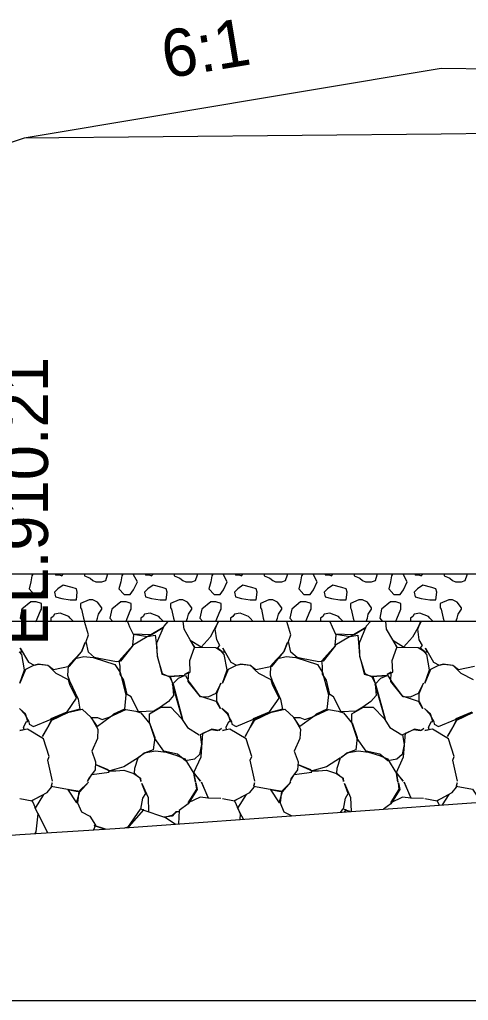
# Model space of a CAD drawing. Extents: x -26 to 4781, y -31 to 24738.
# Drawn here: x 2269.09 to 2278.57, y 7500 to 7520.71 of the extents above; entities that cross this region are included whole.
import ezdxf

# ---------------------------------------------------------------- set-up
doc = ezdxf.new("R2010")
doc.units = 0
for name, color, linetype in [('DESIGN - SHEET - Light Grid', 7, 'Continuous'), ('DESIGN - TRANSPORTATION - Proposed Layout Patterning', 7, 'Continuous'), ('DESIGN - TYPICAL - Finished Grade and Subgrade', 7, 'Continuous'), ('DESIGN - TYPICAL - Finished Grade Slopes Text', 7, 'Continuous'), ('DESIGN - TYPICAL - Subgrade Tie Text', 7, 'Continuous'), ('GEOTECHNICAL – SCRATCH – Level 1', 7, 'Continuous'), ('SURVEY - GROUND - Top of Ground', 7, 'Continuous')]:
    doc.layers.add(name, color=color, linetype=linetype)

msp = doc.modelspace()

# ---------------------------------------------------------------- linework, layer by layer
at = {"layer": 'DESIGN - SHEET - Light Grid'}
msp.add_line((2000, 7500), (2300, 7500), dxfattribs=at)
at = {"layer": 'DESIGN - TRANSPORTATION - Proposed Layout Patterning'}
for p, q in [((2269.33, 7508.419), (2269.14, 7508.259)), ((2271.23, 7508.419), (2271.04, 7508.259)), ((2273.13, 7508.419), (2272.94, 7508.259)), ((2275.03, 7508.419), (2274.84, 7508.259)), ((2276.93, 7508.419), (2276.74, 7508.259)), ((2270.38, 7508.289), (2270.4, 7508.259)), ((2272.28, 7508.289), (2272.3, 7508.259)), ((2274.18, 7508.289), (2274.2, 7508.259)), ((2276.08, 7508.289), (2276.1, 7508.259)), ((2277.98, 7508.289), (2278, 7508.259))]:
    msp.add_line(p, q, dxfattribs=at)
for points in [[(2269.33, 7508.839), (2269.29, 7508.689), (2269.4, 7508.569), (2269.53, 7508.569), (2269.6, 7508.669), (2269.68, 7508.839), (2269.6, 7508.989), (2269.589, 7509)], [(2269.373, 7509), (2269.35, 7508.969), (2269.33, 7508.839)], [(2269.845, 7509), (2269.85, 7508.989), (2269.93, 7508.989), (2269.98, 7508.969), (2270.011, 7509)], [(2270.46, 7509), (2270.46, 7508.969), (2270.53, 7508.939), (2270.58, 7508.919), (2270.64, 7508.869)], [(2270.64, 7508.869), (2270.7, 7508.839), (2270.83, 7508.839), (2270.91, 7508.869), (2270.95, 7508.989), (2270.95, 7509)], [(2271.23, 7508.839), (2271.19, 7508.689), (2271.3, 7508.569), (2271.43, 7508.569), (2271.5, 7508.669), (2271.58, 7508.839), (2271.5, 7508.989), (2271.489, 7509)], [(2271.273, 7509), (2271.25, 7508.969), (2271.23, 7508.839)], [(2271.745, 7509), (2271.75, 7508.989), (2271.83, 7508.989), (2271.88, 7508.969), (2271.911, 7509)], [(2272.36, 7509), (2272.36, 7508.969), (2272.43, 7508.939), (2272.48, 7508.919), (2272.54, 7508.869)], [(2272.54, 7508.869), (2272.6, 7508.839), (2272.73, 7508.839), (2272.81, 7508.869), (2272.85, 7508.989), (2272.85, 7509)], [(2273.13, 7508.839), (2273.09, 7508.689), (2273.2, 7508.569), (2273.33, 7508.569), (2273.4, 7508.669), (2273.48, 7508.839), (2273.4, 7508.989), (2273.389, 7509)], [(2273.173, 7509), (2273.15, 7508.969), (2273.13, 7508.839)], [(2273.645, 7509), (2273.65, 7508.989), (2273.73, 7508.989), (2273.78, 7508.969), (2273.811, 7509)], [(2274.26, 7509), (2274.26, 7508.969), (2274.33, 7508.939), (2274.38, 7508.919), (2274.44, 7508.869)], [(2274.44, 7508.869), (2274.5, 7508.839), (2274.63, 7508.839), (2274.71, 7508.869), (2274.75, 7508.989), (2274.75, 7509)], [(2275.03, 7508.839), (2274.99, 7508.689), (2275.1, 7508.569), (2275.23, 7508.569), (2275.3, 7508.669), (2275.38, 7508.839), (2275.3, 7508.989), (2275.289, 7509)], [(2275.073, 7509), (2275.05, 7508.969), (2275.03, 7508.839)], [(2275.545, 7509), (2275.55, 7508.989), (2275.63, 7508.989), (2275.68, 7508.969), (2275.711, 7509)], [(2276.16, 7509), (2276.16, 7508.969), (2276.23, 7508.939), (2276.28, 7508.919), (2276.34, 7508.869)], [(2276.34, 7508.869), (2276.4, 7508.839), (2276.53, 7508.839), (2276.61, 7508.869), (2276.65, 7508.989), (2276.65, 7509)], [(2276.93, 7508.839), (2276.89, 7508.689), (2277, 7508.569), (2277.13, 7508.569), (2277.2, 7508.669), (2277.28, 7508.839), (2277.2, 7508.989), (2277.189, 7509)], [(2276.973, 7509), (2276.95, 7508.969), (2276.93, 7508.839)], [(2277.445, 7509), (2277.45, 7508.989), (2277.53, 7508.989), (2277.58, 7508.969), (2277.611, 7509)], [(2278.06, 7509), (2278.06, 7508.969), (2278.13, 7508.939), (2278.18, 7508.919), (2278.24, 7508.869)], [(2278.24, 7508.869), (2278.3, 7508.839), (2278.43, 7508.839), (2278.51, 7508.869), (2278.55, 7508.989), (2278.55, 7509)], [(2270.29, 7508.689), (2270.2, 7508.719), (2270.01, 7508.769), (2269.9, 7508.689), (2269.83, 7508.619), (2269.85, 7508.519), (2269.98, 7508.489), (2270.16, 7508.459), (2270.29, 7508.459), (2270.31, 7508.619), (2270.29, 7508.689)], [(2272.19, 7508.689), (2272.1, 7508.719), (2271.91, 7508.769), (2271.8, 7508.689), (2271.73, 7508.619), (2271.75, 7508.519), (2271.88, 7508.489), (2272.06, 7508.459), (2272.19, 7508.459), (2272.21, 7508.619), (2272.19, 7508.689)], [(2274.09, 7508.689), (2274, 7508.719), (2273.81, 7508.769), (2273.7, 7508.689), (2273.63, 7508.619), (2273.65, 7508.519), (2273.78, 7508.489), (2273.96, 7508.459), (2274.09, 7508.459), (2274.11, 7508.619), (2274.09, 7508.689)], [(2275.99, 7508.689), (2275.9, 7508.719), (2275.71, 7508.769), (2275.6, 7508.689), (2275.53, 7508.619), (2275.55, 7508.519), (2275.68, 7508.489), (2275.86, 7508.459), (2275.99, 7508.459), (2276.01, 7508.619), (2275.99, 7508.689)], [(2277.89, 7508.689), (2277.8, 7508.719), (2277.61, 7508.769), (2277.5, 7508.689), (2277.43, 7508.619), (2277.45, 7508.519), (2277.58, 7508.489), (2277.76, 7508.459), (2277.89, 7508.459), (2277.91, 7508.619), (2277.89, 7508.689)], [(2269.55, 7508.259), (2269.55, 7508.379), (2269.44, 7508.419), (2269.33, 7508.419)], [(2270.64, 7508.459), (2270.58, 7508.459), (2270.56, 7508.459), (2270.38, 7508.379), (2270.38, 7508.289)], [(2270.83, 7508.259), (2270.83, 7508.289), (2270.74, 7508.409), (2270.64, 7508.459)], [(2271.45, 7508.259), (2271.45, 7508.379), (2271.34, 7508.419), (2271.23, 7508.419)], [(2272.54, 7508.459), (2272.48, 7508.459), (2272.46, 7508.459), (2272.28, 7508.379), (2272.28, 7508.289)], [(2272.73, 7508.259), (2272.73, 7508.289), (2272.64, 7508.409), (2272.54, 7508.459)], [(2273.35, 7508.259), (2273.35, 7508.379), (2273.24, 7508.419), (2273.13, 7508.419)], [(2274.44, 7508.459), (2274.38, 7508.459), (2274.36, 7508.459), (2274.18, 7508.379), (2274.18, 7508.289)], [(2274.63, 7508.259), (2274.63, 7508.289), (2274.54, 7508.409), (2274.44, 7508.459)], [(2275.25, 7508.259), (2275.25, 7508.379), (2275.14, 7508.419), (2275.03, 7508.419)], [(2276.34, 7508.459), (2276.28, 7508.459), (2276.26, 7508.459), (2276.08, 7508.379), (2276.08, 7508.289)], [(2276.53, 7508.259), (2276.53, 7508.289), (2276.44, 7508.409), (2276.34, 7508.459)], [(2277.15, 7508.259), (2277.15, 7508.379), (2277.04, 7508.419), (2276.93, 7508.419)], [(2278.24, 7508.459), (2278.18, 7508.459), (2278.16, 7508.459), (2277.98, 7508.379), (2277.98, 7508.289)], [(2278.43, 7508.259), (2278.43, 7508.289), (2278.34, 7508.409), (2278.24, 7508.459)], [(2269.14, 7508.259), (2269.1, 7508.069), (2269.163, 7508)], [(2269.429, 7508), (2269.44, 7508.009), (2269.53, 7508.229), (2269.55, 7508.259)], [(2270.13, 7508.109), (2269.95, 7508.179), (2269.83, 7508.159), (2269.8, 7508.109), (2269.75, 7508.069), (2269.75, 7508)], [(2270.4, 7508.259), (2270.44, 7508.069), (2270.462, 7508)], [(2270.712, 7508), (2270.74, 7508.069), (2270.76, 7508.159), (2270.83, 7508.259)], [(2271.04, 7508.259), (2271, 7508.069), (2271.063, 7508)], [(2271.329, 7508), (2271.34, 7508.009), (2271.43, 7508.229), (2271.45, 7508.259)], [(2272.03, 7508.109), (2271.85, 7508.179), (2271.73, 7508.159), (2271.7, 7508.109), (2271.65, 7508.069), (2271.65, 7508)], [(2272.3, 7508.259), (2272.34, 7508.069), (2272.362, 7508)], [(2272.612, 7508), (2272.64, 7508.069), (2272.66, 7508.159), (2272.73, 7508.259)], [(2272.94, 7508.259), (2272.9, 7508.069), (2272.963, 7508)], [(2273.229, 7508), (2273.24, 7508.009), (2273.33, 7508.229), (2273.35, 7508.259)], [(2273.93, 7508.109), (2273.75, 7508.179), (2273.63, 7508.159), (2273.6, 7508.109), (2273.55, 7508.069), (2273.55, 7508)], [(2274.2, 7508.259), (2274.24, 7508.069), (2274.262, 7508)], [(2274.512, 7508), (2274.54, 7508.069), (2274.56, 7508.159), (2274.63, 7508.259)], [(2274.84, 7508.259), (2274.8, 7508.069), (2274.863, 7508)], [(2275.129, 7508), (2275.14, 7508.009), (2275.23, 7508.229), (2275.25, 7508.259)], [(2275.83, 7508.109), (2275.65, 7508.179), (2275.53, 7508.159), (2275.5, 7508.109), (2275.45, 7508.069), (2275.45, 7508)], [(2276.1, 7508.259), (2276.14, 7508.069), (2276.162, 7508)], [(2276.412, 7508), (2276.44, 7508.069), (2276.46, 7508.159), (2276.53, 7508.259)], [(2276.74, 7508.259), (2276.7, 7508.069), (2276.763, 7508)], [(2277.029, 7508), (2277.04, 7508.009), (2277.13, 7508.229), (2277.15, 7508.259)], [(2277.73, 7508.109), (2277.55, 7508.179), (2277.43, 7508.159), (2277.4, 7508.109), (2277.35, 7508.069), (2277.35, 7508)], [(2278, 7508.259), (2278.04, 7508.069), (2278.062, 7508)], [(2278.312, 7508), (2278.34, 7508.069), (2278.36, 7508.159), (2278.43, 7508.259)], [(2270.229, 7508), (2270.16, 7508.069), (2270.13, 7508.109)], [(2271.367, 7508), (2271.415, 7507.891), (2271.495, 7507.721), (2271.475, 7507.501), (2271.785, 7507.681), (2271.895, 7507.731), (2272.125, 7507.871), (2271.865, 7507.721), (2271.495, 7507.731), (2271.795, 7507.681), (2271.955, 7507.711), (2271.975, 7507.561), (2271.995, 7507.281), (2272.095, 7506.891), (2272.275, 7506.841), (2272.325, 7506.691), (2272.345, 7506.441), (2272.235, 7506.311), (2272.065, 7506.191), (2271.925, 7506.111), (2271.605, 7506.091), (2271.445, 7506.411), (2271.365, 7506.461), (2271.295, 7506.761), (2271.215, 7506.891), (2271.215, 7507.061), (2271.195, 7507.171), (2271.485, 7507.491), (2271.225, 7507.161), (2271.135, 7507.151), (2270.765, 7507.221), (2270.675, 7507.241), (2270.545, 7507.351), (2270.495, 7507.581), (2270.545, 7507.721), (2270.459, 7508)], [(2272.224, 7508), (2272.135, 7507.901), (2271.985, 7507.541), (2271.995, 7507.271), (2272.105, 7506.901), (2272.255, 7506.831), (2272.335, 7506.681), (2272.535, 7505.941), (2272.325, 7506.681), (2272.445, 7506.801), (2272.575, 7506.861), (2272.245, 7506.841), (2272.595, 7506.861), (2272.675, 7506.721), (2272.895, 7506.431), (2273.255, 7506.311), (2273.335, 7506.161), (2273.255, 7506.301), (2273.255, 7506.481), (2273.345, 7506.701), (2273.235, 7506.481), (2273.065, 7506.401), (2272.915, 7506.411), (2272.655, 7506.731), (2272.665, 7506.931), (2272.575, 7506.881), (2272.695, 7506.931), (2272.685, 7507.181), (2272.785, 7507.451), (2272.965, 7507.461), (2273.235, 7507.451), (2273.365, 7507.371), (2273.275, 7507.441), (2273.325, 7507.491), (2273.255, 7507.611), (2273.225, 7507.841), (2273.285, 7507.991), (2273.294, 7508)], [(2272.129, 7508), (2272.06, 7508.069), (2272.03, 7508.109)], [(2273.294, 7508), (2273.195, 7507.821), (2273.115, 7507.671), (2272.925, 7507.461), (2272.695, 7507.601), (2272.785, 7507.461), (2272.695, 7507.611), (2272.565, 7507.841), (2272.548, 7508)], [(2274.029, 7508), (2273.96, 7508.069), (2273.93, 7508.109)], [(2275.647, 7508), (2275.695, 7507.891), (2275.775, 7507.721), (2275.755, 7507.501), (2276.065, 7507.681), (2276.175, 7507.731), (2276.405, 7507.871), (2276.145, 7507.721), (2275.775, 7507.731), (2276.075, 7507.681), (2276.235, 7507.711), (2276.255, 7507.561), (2276.275, 7507.281), (2276.375, 7506.891), (2276.555, 7506.841), (2276.605, 7506.691), (2276.625, 7506.441), (2276.515, 7506.311), (2276.345, 7506.191), (2276.205, 7506.111), (2275.885, 7506.091), (2275.725, 7506.411), (2275.645, 7506.461), (2275.575, 7506.761), (2275.495, 7506.891), (2275.495, 7507.061), (2275.475, 7507.171), (2275.765, 7507.491), (2275.505, 7507.161), (2275.415, 7507.151), (2275.045, 7507.221), (2274.955, 7507.241), (2274.825, 7507.351), (2274.775, 7507.581), (2274.825, 7507.721), (2274.739, 7508)], [(2275.929, 7508), (2275.86, 7508.069), (2275.83, 7508.109)], [(2276.504, 7508), (2276.415, 7507.901), (2276.265, 7507.541), (2276.275, 7507.271), (2276.385, 7506.901), (2276.535, 7506.831), (2276.615, 7506.681), (2276.815, 7505.941), (2276.605, 7506.681), (2276.725, 7506.801), (2276.855, 7506.861), (2276.525, 7506.841), (2276.875, 7506.861), (2276.955, 7506.721), (2277.175, 7506.431), (2277.535, 7506.311), (2277.615, 7506.161), (2277.535, 7506.301), (2277.535, 7506.481), (2277.625, 7506.701), (2277.515, 7506.481), (2277.345, 7506.401), (2277.195, 7506.411), (2276.935, 7506.731), (2276.945, 7506.931), (2276.855, 7506.881), (2276.975, 7506.931), (2276.965, 7507.181), (2277.065, 7507.451), (2277.245, 7507.461), (2277.515, 7507.451), (2277.645, 7507.371), (2277.555, 7507.441), (2277.605, 7507.491), (2277.535, 7507.611), (2277.505, 7507.841), (2277.565, 7507.991), (2277.574, 7508)], [(2277.574, 7508), (2277.475, 7507.821), (2277.395, 7507.671), (2277.205, 7507.461), (2276.975, 7507.601), (2277.065, 7507.461), (2276.975, 7507.611), (2276.845, 7507.841), (2276.828, 7508)], [(2277.829, 7508), (2277.76, 7508.069), (2277.73, 7508.109)], [(2269.785, 7504.631), (2269.685, 7505.071), (2269.715, 7505.151), (2269.595, 7505.521), (2269.255, 7505.731), (2269.095, 7505.701), (2269.185, 7505.721), (2269.175, 7505.771), (2269.235, 7505.891), (2269.265, 7505.891), (2269.215, 7506.051), (2269.085, 7506.161), (2269.195, 7506.051), (2269.285, 7505.891), (2269.295, 7505.831), (2269.385, 7505.781), (2269.755, 7505.941), (2270.105, 7506.071), (2269.765, 7505.911), (2269.685, 7505.771), (2269.575, 7505.571), (2269.685, 7505.761), (2269.755, 7505.911), (2269.755, 7505.951), (2270.095, 7506.091), (2270.295, 7506.381), (2270.155, 7506.671), (2270.125, 7506.771), (2269.865, 7506.901), (2269.785, 7506.981), (2269.695, 7507.071), (2269.485, 7507.101), (2269.385, 7507.071), (2269.215, 7506.991), (2269.095, 7506.701), (2269.195, 7506.981), (2269.135, 7507.301), (2269.085, 7507.361), (2269.145, 7507.361), (2269.105, 7507.441), (2269.275, 7507.141), (2269.395, 7507.081), (2269.495, 7507.101), (2269.685, 7507.081), (2269.805, 7506.991), (2270.145, 7507.061), (2270.395, 7507.361), (2270.475, 7507.561), (2270.395, 7507.361), (2270.235, 7507.191), (2270.115, 7507.061), (2270.105, 7506.871), (2270.145, 7506.751), (2270.325, 7506.361), (2270.365, 7506.151), (2270.105, 7506.081), (2270.415, 7506.151), (2270.605, 7505.971), (2270.745, 7505.731), (2270.735, 7505.531), (2270.615, 7505.261), (2270.695, 7505.041), (2270.685, 7504.871), (2270.545, 7504.681), (2270.525, 7504.621), (2270.615, 7504.771), (2270.985, 7504.821), (2270.965, 7504.871), (2270.705, 7504.971), (2270.995, 7504.851), (2271.125, 7504.851), (2271.295, 7504.861), (2271.505, 7504.791), (2271.645, 7504.691), (2271.655, 7504.621), (2271.645, 7504.681), (2271.515, 7504.801), (2271.525, 7504.901), (2271.595, 7505.121), (2271.295, 7504.931), (2270.995, 7504.851)], [(2274.065, 7504.631), (2273.965, 7505.071), (2273.995, 7505.151), (2273.875, 7505.521), (2273.535, 7505.731), (2273.375, 7505.701), (2273.465, 7505.721), (2273.455, 7505.771), (2273.515, 7505.891), (2273.545, 7505.891), (2273.495, 7506.051), (2273.365, 7506.161), (2273.475, 7506.051), (2273.565, 7505.891), (2273.575, 7505.831), (2273.665, 7505.781), (2274.035, 7505.941), (2274.385, 7506.071), (2274.045, 7505.911), (2273.965, 7505.771), (2273.855, 7505.571), (2273.965, 7505.761), (2274.035, 7505.911), (2274.035, 7505.951), (2274.375, 7506.091), (2274.575, 7506.381), (2274.435, 7506.671), (2274.405, 7506.771), (2274.145, 7506.901), (2274.065, 7506.981), (2273.975, 7507.071), (2273.765, 7507.101), (2273.665, 7507.071), (2273.495, 7506.991), (2273.375, 7506.701), (2273.475, 7506.981), (2273.415, 7507.301), (2273.365, 7507.361), (2273.425, 7507.361), (2273.385, 7507.441), (2273.555, 7507.141), (2273.675, 7507.081), (2273.775, 7507.101), (2273.965, 7507.081), (2274.085, 7506.991), (2274.425, 7507.061), (2274.675, 7507.361), (2274.755, 7507.561), (2274.675, 7507.361), (2274.515, 7507.191), (2274.395, 7507.061), (2274.385, 7506.871), (2274.425, 7506.751), (2274.605, 7506.361), (2274.645, 7506.151), (2274.385, 7506.081), (2274.695, 7506.151), (2274.885, 7505.971), (2275.025, 7505.731), (2275.015, 7505.531), (2274.895, 7505.261), (2274.975, 7505.041), (2274.965, 7504.871), (2274.825, 7504.681), (2274.805, 7504.621), (2274.895, 7504.771), (2275.265, 7504.821), (2275.245, 7504.871), (2274.985, 7504.971), (2275.275, 7504.851), (2275.405, 7504.851), (2275.575, 7504.861), (2275.785, 7504.791), (2275.925, 7504.691), (2275.935, 7504.621), (2275.925, 7504.681), (2275.795, 7504.801), (2275.805, 7504.901), (2275.875, 7505.121), (2275.575, 7504.931), (2275.275, 7504.851)], [(2278.685, 7506.771), (2278.425, 7506.901), (2278.345, 7506.981), (2278.255, 7507.071), (2278.045, 7507.101), (2277.945, 7507.071), (2277.775, 7506.991), (2277.655, 7506.701), (2277.755, 7506.981), (2277.695, 7507.301), (2277.645, 7507.361), (2277.705, 7507.361), (2277.665, 7507.441), (2277.835, 7507.141), (2277.955, 7507.081), (2278.055, 7507.101), (2278.245, 7507.081), (2278.365, 7506.991), (2278.705, 7507.061)], [(2270.265, 7507.221), (2270.445, 7507.261), (2270.645, 7507.241), (2271.105, 7507.091), (2271.215, 7506.921), (2271.335, 7506.451), (2271.305, 7506.151), (2271.075, 7506.041), (2271.005, 7505.981), (2270.735, 7505.781), (2270.605, 7505.971), (2270.735, 7505.971), (2270.835, 7505.931), (2270.985, 7505.981), (2271.335, 7506.141), (2271.545, 7506.111), (2271.655, 7506.071), (2271.845, 7505.841), (2271.945, 7505.551), (2271.915, 7505.291), (2271.745, 7505.231), (2271.605, 7505.131), (2271.725, 7505.231), (2271.965, 7505.271), (2272.185, 7505.241), (2272.415, 7505.171), (2272.585, 7505.101), (2272.775, 7504.791), (2272.805, 7504.611), (2272.775, 7504.801), (2272.915, 7504.631), (2272.775, 7504.811), (2272.925, 7505.141), (2272.965, 7505.641), (2273.145, 7505.721), (2273.275, 7505.701), (2273.355, 7505.741), (2273.305, 7505.701), (2273.155, 7505.731), (2272.985, 7505.641), (2272.905, 7505.611), (2272.935, 7505.401), (2272.895, 7505.191), (2272.785, 7505.091), (2272.595, 7505.061), (2272.425, 7505.201), (2272.135, 7505.261), (2271.945, 7505.531), (2271.835, 7505.871), (2271.835, 7506.051), (2272.075, 7506.191), (2272.285, 7506.191), (2272.515, 7505.951), (2272.635, 7505.761), (2272.885, 7505.611)], [(2274.545, 7507.221), (2274.725, 7507.261), (2274.925, 7507.241), (2275.385, 7507.091), (2275.495, 7506.921), (2275.615, 7506.451), (2275.585, 7506.151), (2275.355, 7506.041), (2275.285, 7505.981), (2275.015, 7505.781), (2274.885, 7505.971), (2275.015, 7505.971), (2275.115, 7505.931), (2275.265, 7505.981), (2275.615, 7506.141), (2275.825, 7506.111), (2275.935, 7506.071), (2276.125, 7505.841), (2276.225, 7505.551), (2276.195, 7505.291), (2276.025, 7505.231), (2275.885, 7505.131), (2276.005, 7505.231), (2276.245, 7505.271), (2276.465, 7505.241), (2276.695, 7505.171), (2276.865, 7505.101), (2277.055, 7504.791), (2277.085, 7504.611), (2277.055, 7504.801), (2277.195, 7504.631), (2277.055, 7504.811), (2277.205, 7505.141), (2277.245, 7505.641), (2277.425, 7505.721), (2277.555, 7505.701), (2277.635, 7505.741), (2277.585, 7505.701), (2277.435, 7505.731), (2277.265, 7505.641), (2277.185, 7505.611), (2277.215, 7505.401), (2277.175, 7505.191), (2277.065, 7505.091), (2276.875, 7505.061), (2276.705, 7505.201), (2276.415, 7505.261), (2276.225, 7505.531), (2276.115, 7505.871), (2276.115, 7506.051), (2276.355, 7506.191), (2276.565, 7506.191), (2276.795, 7505.951), (2276.915, 7505.761), (2277.165, 7505.611)], [(2278.345, 7504.631), (2278.245, 7505.071), (2278.275, 7505.151), (2278.155, 7505.521), (2277.815, 7505.731), (2277.655, 7505.701), (2277.745, 7505.721), (2277.735, 7505.771), (2277.795, 7505.891), (2277.825, 7505.891), (2277.775, 7506.051), (2277.645, 7506.161), (2277.755, 7506.051), (2277.845, 7505.891), (2277.855, 7505.831), (2277.945, 7505.781), (2278.315, 7505.941), (2278.665, 7506.071), (2278.325, 7505.911), (2278.245, 7505.771), (2278.135, 7505.571), (2278.245, 7505.761), (2278.315, 7505.911), (2278.315, 7505.951), (2278.655, 7506.091)], [(2269.095, 7504.261), (2269.355, 7504.211), (2269.425, 7504.061), (2269.605, 7504.351), (2269.345, 7504.211), (2269.675, 7504.391), (2269.765, 7504.501), (2269.775, 7504.591), (2269.755, 7504.521), (2270.105, 7504.461), (2270.295, 7504.171), (2270.365, 7504.411), (2270.105, 7504.451), (2270.365, 7504.401), (2270.545, 7504.611), (2270.345, 7504.411), (2270.315, 7504.171), (2270.395, 7503.981), (2270.575, 7503.891), (2270.695, 7503.701), (2270.652, 7503.601)], [(2272.38, 7503.721), (2272.155, 7503.871), (2272.315, 7503.911), (2272.415, 7503.991), (2272.465, 7503.981), (2272.395, 7503.981), (2272.315, 7503.891), (2272.135, 7503.871), (2271.725, 7504.011), (2271.655, 7504.041), (2271.695, 7504.271), (2271.755, 7504.371), (2271.675, 7504.581), (2271.805, 7504.281), (2271.815, 7503.991)], [(2273.345, 7504.261), (2273.085, 7504.271), (2272.935, 7504.611), (2273.075, 7504.271), (2272.905, 7504.291), (2272.655, 7504.171), (2272.835, 7504.461), (2272.815, 7504.591), (2272.845, 7504.451), (2272.655, 7504.151), (2272.465, 7504.011), (2272.445, 7503.726)], [(2273.375, 7504.261), (2273.635, 7504.211), (2273.705, 7504.061), (2273.885, 7504.351), (2273.625, 7504.211), (2273.955, 7504.391), (2274.045, 7504.501), (2274.055, 7504.591), (2274.035, 7504.521), (2274.385, 7504.461), (2274.575, 7504.171), (2274.645, 7504.411), (2274.385, 7504.451), (2274.645, 7504.401), (2274.825, 7504.611), (2274.625, 7504.411), (2274.595, 7504.171), (2274.675, 7503.981), (2274.843, 7503.897)], [(2276.079, 7503.986), (2276.005, 7504.011), (2275.935, 7504.041), (2275.975, 7504.271), (2276.035, 7504.371), (2275.955, 7504.581), (2276.085, 7504.281), (2276.095, 7503.991)], [(2277.625, 7504.261), (2277.365, 7504.271), (2277.215, 7504.611), (2277.355, 7504.271), (2277.185, 7504.291), (2276.935, 7504.171), (2277.115, 7504.461), (2277.095, 7504.591), (2277.125, 7504.451), (2276.935, 7504.151), (2276.779, 7504.037)], [(2278.026, 7504.127), (2278.165, 7504.351), (2277.905, 7504.211), (2278.235, 7504.391), (2278.325, 7504.501), (2278.335, 7504.591), (2278.315, 7504.521), (2278.665, 7504.461), (2278.846, 7504.186)], [(2277.655, 7504.261), (2277.915, 7504.211), (2277.957, 7504.122)], [(2269.686, 7503.54), (2269.475, 7503.951), (2269.415, 7504.071), (2269.475, 7503.941), (2269.435, 7503.561), (2269.41, 7503.522)], [(2271.311, 7503.645), (2271.405, 7503.671), (2271.715, 7504.021), (2271.635, 7504.041), (2271.37, 7503.649)], [(2273.82, 7503.824), (2273.755, 7503.951), (2273.695, 7504.071), (2273.755, 7503.941), (2273.742, 7503.819)], [(2275.956, 7503.977), (2275.995, 7504.021), (2275.915, 7504.041), (2275.867, 7503.971)], [(2270.903, 7503.618), (2270.665, 7503.691), (2270.899, 7503.617)]]:
    msp.add_lwpolyline(points, dxfattribs=at)
at = {"layer": 'DESIGN - TYPICAL - Finished Grade and Subgrade'}
for p, q in [((2278, 7519.676), (2269.19, 7518.208)), ((2288, 7519.606), (2278, 7519.676)), ((2288, 7518.396), (2278, 7518.296)), ((2269.19, 7518.208), (2218.964, 7501.466)), ((2278, 7518.296), (2269.19, 7518.208))]:
    msp.add_line(p, q, dxfattribs=at)
at = {"layer": 'GEOTECHNICAL – SCRATCH – Level 1'}
for p, q in [((2324.862, 7509), (2241.566, 7509)), ((2319.077, 7508), (2238.566, 7508))]:
    msp.add_line(p, q, dxfattribs=at)
at = {"layer": 'SURVEY - GROUND - Top of Ground'}
msp.add_lwpolyline([(2232.778, 7501.714), (2238.696, 7501.885), (2241.042, 7502.025), (2244.191, 7502.138), (2249.095, 7502.401), (2252.275, 7502.563), (2254.39, 7502.707), (2256.093, 7502.765), (2261.783, 7503.075), (2266.167, 7503.288), (2269.095, 7503.502), (2271.11, 7503.631), (2275.612, 7503.952), (2279.326, 7504.221), (2283.028, 7504.47), (2285.227, 7504.656), (2289.342, 7505.009), (2298.527, 7505.717), (2300, 7505.834), (2303.265, 7506.093), (2308.549, 7506.644), (2310.698, 7506.867), (2312.275, 7507.065), (2321.197, 7508.291)], dxfattribs=at)

# ---------------------------------------------------------------- texts
at = {"layer": 'DESIGN - TYPICAL - Finished Grade Slopes Text'}
msp.add_text('6:1', height=1, rotation=9.4623, dxfattribs=at).set_placement((2272.183, 7519.467))
at = {"layer": 'DESIGN - TYPICAL - Subgrade Tie Text'}
msp.add_text('EL.910.21', height=1, rotation=90, dxfattribs=at).set_placement((2269.69, 7507.489))

doc.saveas('drawing.dxf')
